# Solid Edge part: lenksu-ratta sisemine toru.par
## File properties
Title: lenksu-ratta sisemine toru
Author: Stella-Marii
Template: Iso Metric Part.par
Last saved by: Stella-Marii
Revision: 5
Application: Solid Edge
Density: 7833,000 kg/m^3
Accuracy: 0,990
Username: Stella-Marii
Document Number: 23
Material: Steel, structural
Face Style: Steel
Fill Style: ANSI32(Steel)
Virtual Style: Brushed steel
Grouping: Metals\Steel
LibraryName: Materials
Coef. of Thermal Exp: 1.3e-05
Thermal Conductivity: 32.0
Specific Heat: 481.0
Modulus of Elasticity: 199947953000.0
Poisson's Ratio: 0.29
Yield Stress: 262000766.0
Ultimate Stress: 358527364.0
Elongation: 0.0
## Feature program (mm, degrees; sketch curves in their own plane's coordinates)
sketch for "unnamed Protrusion 1" plane through (0, 0, 0) normal (0, 0, 1) x-axis (1, 0, 0)
  circle centre (0, 0) radius 10
extrude "unnamed Protrusion 1" add finite 1045 along +normal
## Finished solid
Body 1: solid body, 3 faces, 2 edges, 0 vertices.
  Faces by surface: plane 2, cylinder 1
  Edges by curve: circle 2
Bounding box of the edges (mm): 20.000 x 20.000 x 1045.000, from (-10, -10, 0) to (10, 10, 1045).
Cylindrical faces by radius (mm): R10 x1
Planar faces by outward normal: +z 1, -z 1
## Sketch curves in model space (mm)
circle centre (0, 0, 0) radius 10
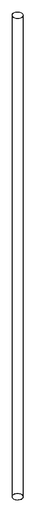
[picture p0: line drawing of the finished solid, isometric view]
